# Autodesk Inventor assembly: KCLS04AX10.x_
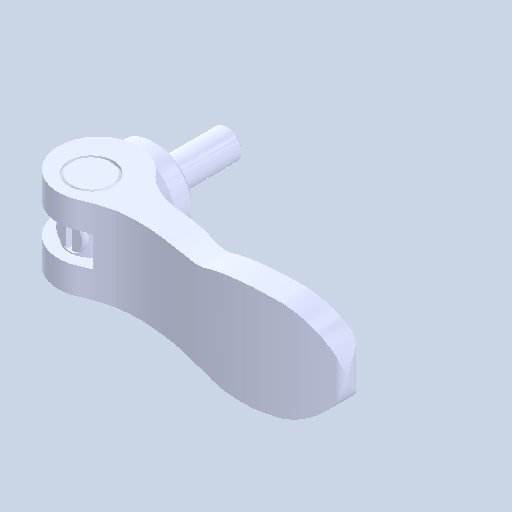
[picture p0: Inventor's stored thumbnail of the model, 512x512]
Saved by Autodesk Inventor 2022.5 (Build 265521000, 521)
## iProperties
Created: 2024-08
Part Number: KCLS04AX10.x_
Document SubType Name: Assembly
Designer: ImaoCorp
Author: ImaoCorp
Sending System: SOLIDWORKS 2022-2022290
MC: AMD64
MC_MODEL: Intel64 Family 6 Model 60 Stepping 3, GenuineIntel
OS: Windows_NT
FRU: Parasolid Version 33.1, build 260,  4-25-2022
FORMAT: text
GUISE: transmit
KEY: FILEKCLS04AX10.x_t
DATE: Thu Aug 29 10:54:05 2024
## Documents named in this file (5)
- Y:\5.更新分\2024年対応\1001_KCL\データ\kcls04ax10\KCLS04AX10.x_.iam
- Y:\5.更新分\2024年対応\1001_KCL\データ\kcls04ax10\KCLS04AX10_01.ipt
- Y:\5.更新分\2024年対応\1001_KCL\データ\kcls04ax10\KCLS04AX10_02.ipt
- Y:\5.更新分\2024年対応\1001_KCL\データ\kcls04ax10\KCLS04AX10_03.ipt
- Y:\5.更新分\2024年対応\1001_KCL\データ\kcls04ax10\KCLS04AX10_04.ipt
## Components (4 placed, 4 different names)
1. KCLS04AX10_01
2. KCLS04AX10_02
3. KCLS04AX10_03
4. KCLS04AX10_04
